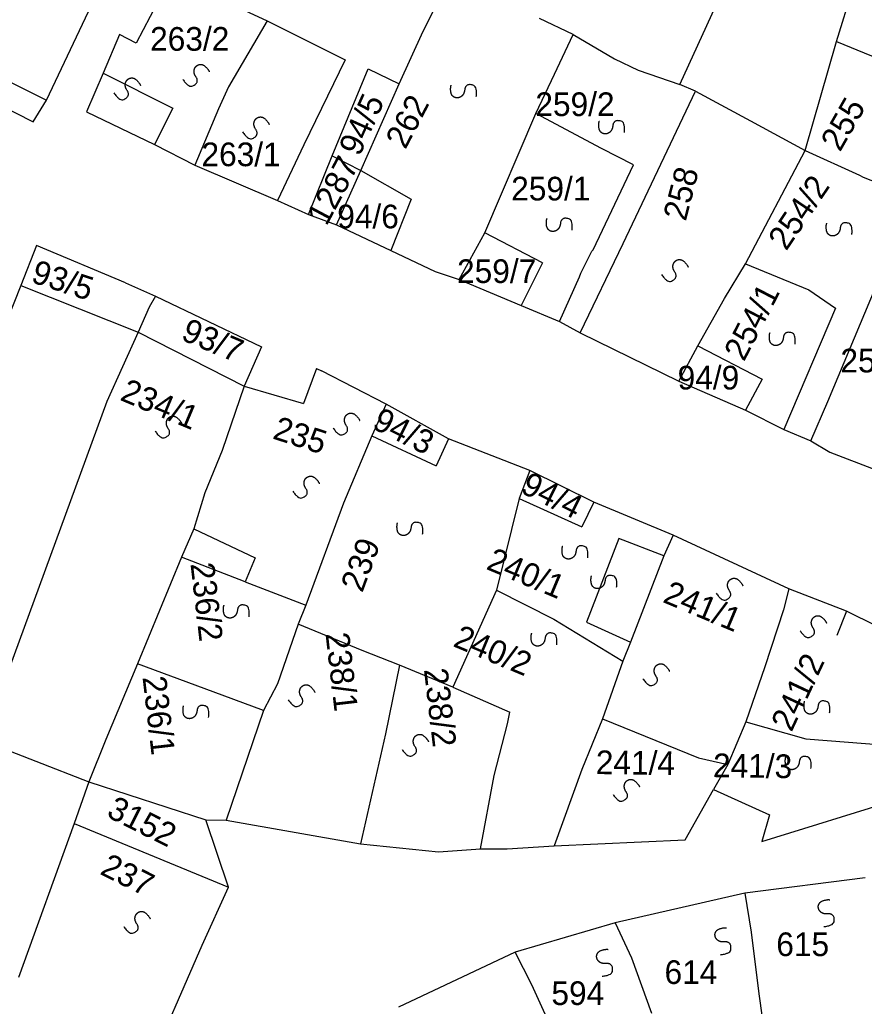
# Model space of a CAD drawing. Extents: x -581999 to -572728, y -1219553 to -1212032.
# Drawn here: x -578031.4 to -577960.1, y -1215897.1 to -1215813.7 of the extents above; entities that cross this region are included whole.
import ezdxf

# ---------------------------------------------------------------- set-up
doc = ezdxf.new("R2010")
doc.units = 0
for name, color, linetype in [('Vrstva 1', 7, 'Continuous'), ('Vrstva 2', 7, 'Continuous'), ('Vrstva 4', 7, 'Continuous'), ('Vrstva 6', 7, 'Continuous')]:
    doc.layers.add(name, color=color, linetype=linetype)

msp = doc.modelspace()

# ---------------------------------------------------------------- linework, layer by layer
at = {"layer": 'Vrstva 1'}
for p, q in [((-578005.031, -1215825.245), (-578001.997, -1215817.89)), ((-578001.997, -1215817.89), (-577999.374, -1215819.155)), ((-578007.054, -1215830.191), (-578005.031, -1215825.245)), ((-578005.031, -1215825.245), (-578002.624, -1215826.465)), ((-577989.233, -1215854.185), (-577983.939, -1215856.565)), ((-577982.94, -1215854.486), (-577983.939, -1215856.565)), ((-577977.028, -1215859.03), (-577979.818, -1215866.311)), ((-577979.818, -1215866.311), (-577980.481, -1215867.917)), ((-577994.856, -1215870.13), (-577990.025, -1215872.245)), ((-577990.233, -1215873.23), (-577990.025, -1215872.245)), ((-577982.2, -1215872.807), (-577974.081, -1215876.088)), ((-577970.084, -1215873.042), (-577965.024, -1215874.479)), ((-577965.024, -1215874.479), (-577955.221, -1215875.268)), ((-577974.081, -1215876.088), (-577971.598, -1215876.666)), ((-577988.161, -1215895.264), (-577989.565, -1215892.527)), ((-577985.873, -1215900.321), (-577988.161, -1215895.264))]:
    msp.add_line(p, q, dxfattribs=at)
for points in [[(-577975.675, -1215819.216), (-577966.075, -1215798.25)], [(-577962.426, -1215815.588), (-577958.277, -1215802.201)], [(-577997.344, -1215814.688), (-577994.909, -1215809.816)], [(-578018.64, -1215810.049), (-578021.602, -1215815.725)], [(-578017.337, -1215810.659), (-578010.541, -1215813.841)], [(-578029.17, -1215820.526), (-578025.385, -1215812.515)], [(-578010.541, -1215813.841), (-578013.79, -1215819.401)], [(-578010.541, -1215813.841), (-578003.949, -1215817.111)], [(-577984.686, -1215814.992), (-577987.511, -1215813.63)], [(-577999.374, -1215819.155), (-577997.344, -1215814.688)], [(-578021.602, -1215815.725), (-578023.016, -1215814.978), (-578024.402, -1215818.252), (-578025.789, -1215821.525)], [(-577986.251, -1215818.326), (-577984.686, -1215814.992)], [(-577984.686, -1215814.992), (-577981.19, -1215817.034)], [(-577965.081, -1215824.77), (-577962.426, -1215815.588)], [(-577962.426, -1215815.588), (-577957.127, -1215817.753)], [(-578038.448, -1215815.919), (-578039.503, -1215817.679), (-578030.313, -1215822.375), (-578029.17, -1215820.526)], [(-578038.448, -1215815.919), (-578029.17, -1215820.526)], [(-578003.949, -1215817.111), (-578007.433, -1215824.309)], [(-577981.19, -1215817.034), (-577979.173, -1215817.987)], [(-577979.173, -1215817.987), (-577975.675, -1215819.216)], [(-577987.817, -1215821.66), (-577986.251, -1215818.326)], [(-578013.79, -1215819.401), (-578014.633, -1215821.254)], [(-578002.624, -1215826.465), (-577999.374, -1215819.155)], [(-577980.462, -1215832.652), (-577974.33, -1215819.761)], [(-577974.33, -1215819.761), (-577975.675, -1215819.216)], [(-577974.33, -1215819.761), (-577969.705, -1215822.266)], [(-578025.789, -1215821.525), (-578020.058, -1215824.269)], [(-578014.633, -1215821.254), (-578016.643, -1215826.017)], [(-577992.152, -1215831.729), (-577987.817, -1215821.66)], [(-577982.286, -1215824.619), (-577987.817, -1215821.66)], [(-577969.705, -1215822.266), (-577965.081, -1215824.77)], [(-578020.058, -1215824.269), (-578016.643, -1215826.017)], [(-578007.433, -1215824.309), (-578009.647, -1215829.016)], [(-577985.836, -1215839.238), (-577984.131, -1215835.47), (-577984.027, -1215835.159), (-577983.096, -1215833.295), (-577982.992, -1215833.19), (-577979.575, -1215825.994), (-577982.286, -1215824.619)], [(-577970.119, -1215834.364), (-577965.081, -1215824.77)], [(-577965.081, -1215824.77), (-577960.474, -1215826.87)], [(-578016.643, -1215826.017), (-578009.647, -1215829.016)], [(-578004.668, -1215831.061), (-578002.624, -1215826.465)], [(-578002.624, -1215826.465), (-577998.362, -1215828.884)], [(-577960.474, -1215826.87), (-577960.47, -1215826.872), (-577960.177, -1215827.043)], [(-577960.177, -1215827.043), (-577955.779, -1215828.757)], [(-578009.647, -1215829.016), (-578007.054, -1215830.191), (-578004.668, -1215831.061)], [(-577998.362, -1215828.884), (-578000.095, -1215833.24)], [(-578004.668, -1215831.061), (-578000.095, -1215833.24)], [(-577994.311, -1215835.694), (-577992.152, -1215831.729)], [(-577987.274, -1215834.274), (-577992.152, -1215831.729)], [(-578030.027, -1215832.796), (-578031.335, -1215836.195)], [(-578022.494, -1215835.975), (-578030.027, -1215832.796)], [(-578000.095, -1215833.24), (-577996.329, -1215835.011), (-577994.311, -1215835.694)], [(-577984.088, -1215840.19), (-577980.462, -1215832.652)], [(-577987.274, -1215834.274), (-577989.064, -1215837.875)], [(-577971.892, -1215837.291), (-577970.119, -1215834.364)], [(-577970.119, -1215834.364), (-577964.769, -1215836.553)], [(-577994.311, -1215835.694), (-577989.064, -1215837.875)], [(-577963.145, -1215845.992), (-577958.653, -1215835.226)], [(-578031.335, -1215836.195), (-578042.221, -1215863.528)], [(-578031.335, -1215836.195), (-578021.434, -1215840.146)], [(-578022.494, -1215835.975), (-578019.975, -1215837.095)], [(-577964.769, -1215836.553), (-577962.507, -1215838.114), (-577966.877, -1215848.36)], [(-578019.975, -1215837.095), (-578020.505, -1215838.022)], [(-578019.975, -1215837.095), (-578011.009, -1215841.366), (-578012.468, -1215844.683)], [(-577974.153, -1215841.3), (-577971.892, -1215837.291)], [(-578020.505, -1215838.022), (-578021.434, -1215840.146)], [(-577989.064, -1215837.875), (-577985.836, -1215839.238)], [(-577985.836, -1215839.238), (-577984.088, -1215840.19)], [(-578021.434, -1215840.146), (-578024.088, -1215845.983)], [(-578021.434, -1215840.146), (-578012.468, -1215844.683)], [(-577984.088, -1215840.19), (-577975.752, -1215844.275)], [(-577975.752, -1215844.275), (-577974.153, -1215841.3)], [(-577974.153, -1215841.3), (-577968.702, -1215844.113)], [(-578006.366, -1215843.192), (-578007.455, -1215846.156)], [(-578006.366, -1215843.192), (-578005.943, -1215843.396)], [(-578000.473, -1215846.212), (-578005.943, -1215843.396)], [(-578012.468, -1215844.683), (-578014.329, -1215850.123)], [(-578012.468, -1215844.683), (-578007.455, -1215846.156)], [(-577975.752, -1215844.275), (-577970.103, -1215846.727)], [(-577968.702, -1215844.113), (-577970.103, -1215846.727)], [(-578024.088, -1215845.983), (-578034.581, -1215874.641)], [(-578000.473, -1215846.212), (-578001.682, -1215848.881)], [(-577995.2, -1215849.146), (-578000.473, -1215846.212)], [(-577964.591, -1215849.313), (-577963.145, -1215845.992)], [(-577970.103, -1215846.727), (-577966.877, -1215848.36)], [(-578001.682, -1215848.881), (-578004.071, -1215854.585)], [(-578001.682, -1215848.881), (-577996.263, -1215851.43)], [(-577966.877, -1215848.36), (-577964.591, -1215849.313)], [(-577995.2, -1215849.146), (-577996.263, -1215851.43)], [(-577988.343, -1215851.819), (-577995.2, -1215849.146)], [(-577964.591, -1215849.313), (-577962.979, -1215850.266), (-577955.583, -1215853.128)], [(-578014.329, -1215850.123), (-578015.789, -1215853.705)], [(-577988.343, -1215851.819), (-577989.233, -1215854.185), (-577991.155, -1215861.919)], [(-577982.94, -1215854.486), (-577988.343, -1215851.819)], [(-578015.789, -1215853.705), (-578016.72, -1215856.757)], [(-578004.071, -1215854.585), (-578007.259, -1215863.208)], [(-577976.217, -1215857.291), (-577982.94, -1215854.486)], [(-578016.72, -1215856.757), (-578017.781, -1215859.144)], [(-577976.217, -1215857.291), (-577977.028, -1215859.03)], [(-577966.465, -1215861.827), (-577976.217, -1215857.291)], [(-578017.781, -1215859.144), (-578021.497, -1215868.165)], [(-578012.387, -1215861.234), (-578017.781, -1215859.144)], [(-578012.387, -1215861.234), (-578007.259, -1215863.208)], [(-577991.155, -1215861.919), (-577994.856, -1215870.13)], [(-577991.155, -1215861.919), (-577986.319, -1215864.391)], [(-577966.465, -1215861.827), (-577966.916, -1215863.598)], [(-577961.589, -1215863.697), (-577966.465, -1215861.827)], [(-578007.259, -1215863.208), (-578007.923, -1215864.8)], [(-577966.916, -1215863.598), (-577968.478, -1215868.394)], [(-577956.449, -1215866.23), (-577961.589, -1215863.697)], [(-578007.923, -1215864.8), (-578009.65, -1215869.841)], [(-578002.501, -1215867.017), (-578007.923, -1215864.8)], [(-577986.319, -1215864.391), (-577980.481, -1215867.917)], [(-577999.353, -1215868.272), (-578002.501, -1215867.017)], [(-578021.497, -1215868.165), (-578024.152, -1215874.532)], [(-578015.866, -1215870.228), (-578021.497, -1215868.165)], [(-577980.481, -1215867.917), (-577982.2, -1215872.807), (-577983.934, -1215877.069)], [(-577999.353, -1215868.272), (-578000.533, -1215874.078)], [(-577994.856, -1215870.13), (-577999.353, -1215868.272)], [(-577968.478, -1215868.394), (-577970.084, -1215873.042), (-577971.598, -1215876.666)], [(-578009.65, -1215869.841), (-578010.844, -1215872.096)], [(-578010.844, -1215872.096), (-578015.866, -1215870.228)], [(-578010.844, -1215872.096), (-578013.998, -1215881.35)], [(-577991.358, -1215877.578), (-577990.233, -1215873.23)], [(-578000.533, -1215874.078), (-578002.653, -1215883.366)], [(-578034.581, -1215874.641), (-578025.612, -1215878.113)], [(-578024.152, -1215874.532), (-578025.612, -1215878.113)], [(-577983.934, -1215877.069), (-577986.292, -1215883.536)], [(-577971.598, -1215876.666), (-577972.809, -1215878.782)], [(-578025.612, -1215878.113), (-578026.852, -1215881.655)], [(-578025.612, -1215878.113), (-578015.714, -1215881.346)], [(-577992.494, -1215883.787), (-577991.358, -1215877.578)], [(-577986.292, -1215883.536), (-577975.208, -1215883.029), (-577972.809, -1215878.782)], [(-577972.809, -1215878.782), (-577968.078, -1215880.922)], [(-577968.078, -1215880.922), (-577968.744, -1215883.177), (-577957.258, -1215879.619)], [(-578013.798, -1215887.029), (-578015.714, -1215881.346)], [(-578015.714, -1215881.346), (-578013.998, -1215881.35)], [(-578013.998, -1215881.35), (-578002.653, -1215883.366)], [(-578026.852, -1215881.655), (-578031.546, -1215894.646)], [(-578026.852, -1215881.655), (-578013.798, -1215887.029)], [(-578002.653, -1215883.366), (-577996.057, -1215884.045)], [(-577996.057, -1215884.045), (-577992.494, -1215883.787)], [(-577992.494, -1215883.787), (-577990.25, -1215883.792)], [(-577990.25, -1215883.792), (-577986.292, -1215883.536)], [(-577959.997, -1215886.222), (-577970.158, -1215887.527)], [(-578016.035, -1215891.935), (-578013.798, -1215887.029)], [(-577970.158, -1215887.527), (-577981.114, -1215890.025)], [(-577970.158, -1215887.527), (-577969.646, -1215890.833), (-577968.976, -1215896.021)], [(-577981.114, -1215890.025), (-577989.565, -1215892.527)], [(-577981.114, -1215890.025), (-577979.734, -1215892.988), (-577978.067, -1215897.664)], [(-578022.888, -1215902.436), (-578020.778, -1215902.839), (-578016.035, -1215891.935)], [(-577989.565, -1215892.527), (-577999.429, -1215897.162)], [(-577968.976, -1215896.021), (-577966.643, -1215912.612)]]:
    msp.add_lwpolyline(points, dxfattribs=at)
at = {"layer": 'Vrstva 4'}
for p, q in [((-577980.817, -1215857.563), (-577983.556, -1215864.639)), ((-577977.028, -1215859.03), (-577980.817, -1215857.563)), ((-577983.556, -1215864.639), (-577979.818, -1215866.311))]:
    msp.add_line(p, q, dxfattribs=at)
for points in [[(-578024.402, -1215818.252), (-578018.504, -1215821.218)], [(-578018.504, -1215821.218), (-578020.058, -1215824.269)], [(-578016.72, -1215856.757), (-578011.548, -1215859.195), (-578012.387, -1215861.234)], [(-577961.589, -1215863.697), (-577962.392, -1215865.768)]]:
    msp.add_lwpolyline(points, dxfattribs=at)
at = {"layer": 'Vrstva 6'}
for points in [[(-578017.662, -1215818.778), (-578017.182, -1215819.485), (-578016.488, -1215819.174), (-578016.411, -1215818.774), (-578016.647, -1215818.429), (-578016.732, -1215818.097), (-578016.65, -1215817.807), (-578016.506, -1215817.627), (-578016.27, -1215817.499), (-578015.905, -1215817.535), (-578015.478, -1215817.974), (-578015.423, -1215818.147)], [(-578023.479, -1215819.919), (-578022.999, -1215820.626), (-578022.305, -1215820.315), (-578022.228, -1215819.915), (-578022.464, -1215819.57), (-578022.549, -1215819.238), (-578022.467, -1215818.948), (-578022.323, -1215818.768), (-578022.087, -1215818.64), (-578021.722, -1215818.676), (-578021.295, -1215819.115), (-578021.24, -1215819.288)], [(-577992.864, -1215820.224), (-577992.769, -1215819.373), (-577993.499, -1215819.161), (-577993.816, -1215819.415), (-577993.861, -1215819.831), (-577994.012, -1215820.138), (-577994.261, -1215820.305), (-577994.488, -1215820.349), (-577994.751, -1215820.293), (-577995.006, -1215820.029), (-577995.046, -1215819.419), (-577994.976, -1215819.25)], [(-578012.605, -1215823.217), (-578012.125, -1215823.924), (-578011.431, -1215823.613), (-578011.354, -1215823.213), (-578011.59, -1215822.868), (-578011.675, -1215822.536), (-578011.593, -1215822.246), (-578011.449, -1215822.066), (-578011.213, -1215821.938), (-578010.848, -1215821.974), (-578010.421, -1215822.413), (-578010.366, -1215822.586)], [(-577980.347, -1215823.268), (-577980.252, -1215822.417), (-577980.982, -1215822.205), (-577981.299, -1215822.459), (-577981.344, -1215822.875), (-577981.495, -1215823.182), (-577981.744, -1215823.349), (-577981.971, -1215823.393), (-577982.234, -1215823.337), (-577982.489, -1215823.073), (-577982.529, -1215822.463), (-577982.459, -1215822.294)], [(-577984.773, -1215831.511), (-577984.678, -1215830.66), (-577985.408, -1215830.448), (-577985.725, -1215830.702), (-577985.77, -1215831.118), (-577985.921, -1215831.425), (-577986.17, -1215831.592), (-577986.397, -1215831.636), (-577986.66, -1215831.58), (-577986.915, -1215831.316), (-577986.955, -1215830.706), (-577986.885, -1215830.537)], [(-577961.128, -1215831.893), (-577961.033, -1215831.042), (-577961.763, -1215830.83), (-577962.08, -1215831.084), (-577962.125, -1215831.5), (-577962.276, -1215831.807), (-577962.525, -1215831.974), (-577962.752, -1215832.018), (-577963.015, -1215831.962), (-577963.27, -1215831.698), (-577963.31, -1215831.088), (-577963.24, -1215830.919)], [(-577977.202, -1215835.265), (-577976.722, -1215835.972), (-577976.028, -1215835.661), (-577975.951, -1215835.261), (-577976.187, -1215834.916), (-577976.272, -1215834.584), (-577976.19, -1215834.294), (-577976.046, -1215834.114), (-577975.81, -1215833.986), (-577975.445, -1215834.022), (-577975.018, -1215834.461), (-577974.963, -1215834.634)], [(-577965.932, -1215841.151), (-577965.837, -1215840.3), (-577966.567, -1215840.088), (-577966.884, -1215840.342), (-577966.929, -1215840.758), (-577967.08, -1215841.065), (-577967.329, -1215841.232), (-577967.556, -1215841.276), (-577967.819, -1215841.22), (-577968.074, -1215840.956), (-577968.114, -1215840.346), (-577968.044, -1215840.177)], [(-578020.001, -1215848.492), (-578019.521, -1215849.199), (-578018.827, -1215848.888), (-578018.75, -1215848.488), (-578018.986, -1215848.143), (-578019.071, -1215847.811), (-578018.989, -1215847.521), (-578018.845, -1215847.341), (-578018.609, -1215847.213), (-578018.244, -1215847.249), (-578017.817, -1215847.688), (-578017.762, -1215847.861)], [(-578004.954, -1215848.238), (-578004.474, -1215848.945), (-578003.78, -1215848.634), (-578003.703, -1215848.234), (-578003.939, -1215847.889), (-578004.024, -1215847.557), (-578003.942, -1215847.267), (-578003.798, -1215847.087), (-578003.562, -1215846.959), (-578003.197, -1215846.995), (-578002.77, -1215847.434), (-578002.715, -1215847.607)], [(-578008.368, -1215853.564), (-578007.888, -1215854.271), (-578007.194, -1215853.96), (-578007.117, -1215853.56), (-578007.353, -1215853.215), (-578007.438, -1215852.883), (-578007.356, -1215852.593), (-578007.212, -1215852.413), (-578006.976, -1215852.285), (-578006.611, -1215852.321), (-578006.184, -1215852.76), (-578006.129, -1215852.933)], [(-577997.397, -1215857.202), (-577997.302, -1215856.351), (-577998.032, -1215856.139), (-577998.349, -1215856.393), (-577998.394, -1215856.809), (-577998.545, -1215857.116), (-577998.794, -1215857.283), (-577999.021, -1215857.327), (-577999.284, -1215857.271), (-577999.539, -1215857.007), (-577999.579, -1215856.397), (-577999.509, -1215856.228)], [(-577983.451, -1215859.189), (-577983.356, -1215858.338), (-577984.086, -1215858.126), (-577984.403, -1215858.38), (-577984.448, -1215858.796), (-577984.599, -1215859.103), (-577984.848, -1215859.27), (-577985.075, -1215859.314), (-577985.338, -1215859.258), (-577985.593, -1215858.994), (-577985.633, -1215858.384), (-577985.563, -1215858.215)], [(-577981.006, -1215861.685), (-577980.911, -1215860.834), (-577981.641, -1215860.622), (-577981.958, -1215860.876), (-577982.003, -1215861.292), (-577982.154, -1215861.599), (-577982.403, -1215861.766), (-577982.63, -1215861.81), (-577982.893, -1215861.754), (-577983.148, -1215861.49), (-577983.188, -1215860.88), (-577983.118, -1215860.711)], [(-577972.586, -1215862.188), (-577972.106, -1215862.895), (-577971.412, -1215862.584), (-577971.335, -1215862.184), (-577971.571, -1215861.839), (-577971.656, -1215861.507), (-577971.574, -1215861.217), (-577971.43, -1215861.037), (-577971.194, -1215860.909), (-577970.829, -1215860.945), (-577970.402, -1215861.384), (-577970.347, -1215861.557)], [(-578012.064, -1215864.177), (-578011.969, -1215863.326), (-578012.699, -1215863.114), (-578013.016, -1215863.368), (-578013.061, -1215863.784), (-578013.212, -1215864.091), (-578013.461, -1215864.258), (-578013.688, -1215864.302), (-578013.951, -1215864.246), (-578014.206, -1215863.982), (-578014.246, -1215863.372), (-578014.176, -1215863.203)], [(-577965.505, -1215865.358), (-577965.025, -1215866.065), (-577964.331, -1215865.754), (-577964.254, -1215865.354), (-577964.49, -1215865.009), (-577964.575, -1215864.677), (-577964.493, -1215864.387), (-577964.349, -1215864.207), (-577964.113, -1215864.079), (-577963.748, -1215864.115), (-577963.321, -1215864.554), (-577963.266, -1215864.727)], [(-577986.063, -1215866.544), (-577985.968, -1215865.693), (-577986.698, -1215865.481), (-577987.015, -1215865.735), (-577987.06, -1215866.151), (-577987.211, -1215866.458), (-577987.46, -1215866.625), (-577987.687, -1215866.669), (-577987.95, -1215866.613), (-577988.205, -1215866.349), (-577988.245, -1215865.739), (-577988.175, -1215865.57)], [(-577978.782, -1215869.417), (-577978.302, -1215870.124), (-577977.608, -1215869.813), (-577977.531, -1215869.413), (-577977.767, -1215869.068), (-577977.852, -1215868.736), (-577977.77, -1215868.446), (-577977.626, -1215868.266), (-577977.39, -1215868.138), (-577977.025, -1215868.174), (-577976.598, -1215868.613), (-577976.543, -1215868.786)], [(-578008.747, -1215871.193), (-578008.267, -1215871.9), (-578007.573, -1215871.589), (-578007.496, -1215871.189), (-578007.732, -1215870.844), (-578007.817, -1215870.512), (-578007.735, -1215870.222), (-578007.591, -1215870.042), (-578007.355, -1215869.914), (-578006.99, -1215869.95), (-578006.563, -1215870.389), (-578006.508, -1215870.562)], [(-577963.005, -1215872.293), (-577962.91, -1215871.442), (-577963.64, -1215871.23), (-577963.957, -1215871.484), (-577964.002, -1215871.9), (-577964.153, -1215872.207), (-577964.402, -1215872.374), (-577964.629, -1215872.418), (-577964.892, -1215872.362), (-577965.147, -1215872.098), (-577965.187, -1215871.488), (-577965.117, -1215871.319)], [(-578015.478, -1215872.674), (-578015.383, -1215871.823), (-578016.113, -1215871.611), (-578016.43, -1215871.865), (-578016.475, -1215872.281), (-578016.626, -1215872.588), (-578016.875, -1215872.755), (-578017.102, -1215872.799), (-578017.365, -1215872.743), (-578017.62, -1215872.479), (-578017.66, -1215871.869), (-578017.59, -1215871.7)], [(-577999.138, -1215875.378), (-577998.658, -1215876.085), (-577997.964, -1215875.774), (-577997.887, -1215875.374), (-577998.123, -1215875.029), (-577998.208, -1215874.697), (-577998.126, -1215874.407), (-577997.982, -1215874.227), (-577997.746, -1215874.099), (-577997.381, -1215874.135), (-577996.954, -1215874.574), (-577996.899, -1215874.747)], [(-577964.586, -1215876.983), (-577964.491, -1215876.132), (-577965.221, -1215875.92), (-577965.538, -1215876.174), (-577965.583, -1215876.59), (-577965.734, -1215876.897), (-577965.983, -1215877.064), (-577966.21, -1215877.108), (-577966.473, -1215877.052), (-577966.728, -1215876.788), (-577966.768, -1215876.178), (-577966.698, -1215876.009)], [(-577981.31, -1215879.182), (-577980.83, -1215879.889), (-577980.136, -1215879.578), (-577980.059, -1215879.178), (-577980.295, -1215878.833), (-577980.38, -1215878.501), (-577980.298, -1215878.211), (-577980.154, -1215878.031), (-577979.918, -1215877.903), (-577979.553, -1215877.939), (-577979.126, -1215878.378), (-577979.071, -1215878.551)], [(-577963.496, -1215890.356), (-577962.645, -1215890.267), (-577962.593, -1215889.509), (-577962.909, -1215889.253), (-577963.325, -1215889.298), (-577963.657, -1215889.216), (-577963.874, -1215889.008), (-577963.965, -1215888.796), (-577963.966, -1215888.527), (-577963.763, -1215888.222), (-577963.175, -1215888.052), (-577962.995, -1215888.085)], [(-578022.656, -1215890.342), (-578022.176, -1215891.049), (-578021.482, -1215890.738), (-578021.405, -1215890.338), (-578021.641, -1215889.993), (-578021.726, -1215889.661), (-578021.644, -1215889.371), (-578021.5, -1215889.191), (-578021.264, -1215889.063), (-578020.899, -1215889.099), (-578020.472, -1215889.538), (-578020.417, -1215889.711)], [(-577972.224, -1215892.727), (-577971.373, -1215892.638), (-577971.321, -1215891.88), (-577971.637, -1215891.624), (-577972.053, -1215891.669), (-577972.385, -1215891.587), (-577972.602, -1215891.379), (-577972.693, -1215891.167), (-577972.694, -1215890.898), (-577972.491, -1215890.593), (-577971.903, -1215890.423), (-577971.723, -1215890.456)], [(-577982.225, -1215894.551), (-577981.374, -1215894.462), (-577981.322, -1215893.704), (-577981.638, -1215893.448), (-577982.054, -1215893.493), (-577982.386, -1215893.411), (-577982.603, -1215893.203), (-577982.694, -1215892.991), (-577982.695, -1215892.722), (-577982.492, -1215892.417), (-577981.904, -1215892.247), (-577981.724, -1215892.28)]]:
    msp.add_open_spline(points, degree=2, dxfattribs=at)

# ---------------------------------------------------------------- texts
at = {"layer": 'Vrstva 2'}
for s, p in [('263/2', (-578020.424, -1215816.355)), ('259/2', (-577987.872, -1215821.874)), ('263/1', (-578016.083, -1215826.109)), ('259/1', (-577989.911, -1215829.003)), ('94/6', (-578004.611, -1215831.359)), ('259/7', (-577994.488, -1215835.98)), ('253/3', (-577962.093, -1215843.534)), ('94/9', (-577975.85, -1215844.974)), ('615', (-577967.511, -1215892.845)), ('614', (-577976.956, -1215895.201)), ('594', (-577986.513, -1215896.978))]:
    msp.add_text(s, height=2, dxfattribs=at).set_placement(p)
for s, rotation, p in [('94/5', 65.71366, (-578002.729, -1215825.352)), ('262', 62.3651, (-577998.85, -1215824.752)), ('255', 60.20178, (-577962.128, -1215824.969)), ('1287', 61.93404, (-578005.515, -1215831.232)), ('258', 75.54785, (-577975.163, -1215830.82)), ('254/2', 55.90787, (-577966.67, -1215833.327)), ('93/5', 342.07962, (-578030.579, -1215835.885)), ('254/1', 62.57693, (-577970.245, -1215842.682)), ('93/7', 337.27197, (-578017.901, -1215840.742)), ('234/1', 337.27197, (-578023.052, -1215845.837)), ('235', 342.07962, (-578010.158, -1215849.099)), ('94/3', 333.35692, (-578001.757, -1215848.21)), ('94/4', 333.35692, (-577989.222, -1215853.636)), ('239', 69.60819, (-578002.496, -1215862.202)), ('240/1', 337.27197, (-577992.109, -1215860.118)), ('236/2', 276.62328, (-578017.016, -1215859.701)), ('241/1', 337.27197, (-577977.191, -1215862.91)), ('238/1', 276.62328, (-578005.607, -1215865.605)), ('240/2', 337.27197, (-577994.911, -1215866.64)), ('241/2', 64.82967, (-577966.226, -1215873.977)), ('238/2', 276.62328, (-577997.289, -1215868.625)), ('236/1', 276.62328, (-578021.067, -1215869.288)), ('241/4', 359.22562, (-577982.775, -1215877.465)), ('241/3', 359.22562, (-577972.873, -1215877.725)), ('3152', 333.35692, (-578024.197, -1215881.023)), ('237', 333.35692, (-578024.749, -1215885.876))]:
    msp.add_text(s, height=2, rotation=rotation, dxfattribs=at).set_placement(p)

doc.saveas('drawing.dxf')
